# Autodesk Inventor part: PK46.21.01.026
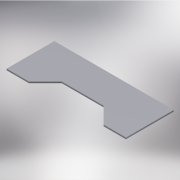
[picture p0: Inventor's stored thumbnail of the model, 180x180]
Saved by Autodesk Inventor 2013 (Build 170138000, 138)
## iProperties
Created: 2005-04
Part Number: PK46.21.01.026
Material: Steel, Mild
Document SubType Name: Modeling
Designer: salex
Manufacturer: Standard
Standards Organization: Custom
Density: 7.86 g/cm^3
Author: salex
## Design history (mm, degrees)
sketch "Эскиз1"
  geometry: L1 (0, 0)-(0, 320); L2 (0, 320)-(800, 320); L3 (800, 320)-(800, 0); L4 (800, 0)-(650, 0); L5 (650, 0)-(540, 110); L6 (540, 110)-(260, 110); L7 (260, 110)-(150, 0); L8 (150, 0)-(0, 0)
  constraints: 16 end point, 4 parallel, 3 equal length, 1 perpendicular, 1 vertical, 1 other
  dimensions: "d0" = 800 distance of L1.end L2.end; "d1" = 110 distance between parallel lines of L6 L8; "d2" = 320 distance of L1.start L1.end; "d3" = 150 distance of L7.end L1.start; "d4" = 260 distance from line of L6.end L1
extrude "Выдавливание1" new body sketch "Эскиз1" distance "d5" = 10; taper "d6" = 0 deg
body "Solid1"
